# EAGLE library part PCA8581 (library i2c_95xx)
128 x 8-Bit EEPROM with I²C Bus Interface
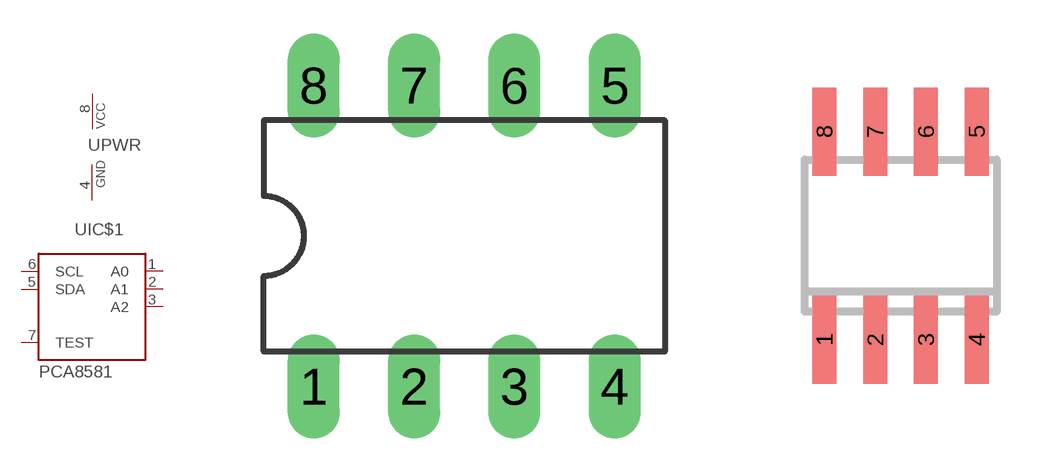
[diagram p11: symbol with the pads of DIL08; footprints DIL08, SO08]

Designator prefix -; gates IC$1=PCA8581 PWR=PWRN

## PCA8581P  [DIL08]
1  IC$1:A0  in
2  IC$1:A1  in
3  IC$1:A2  in
4  PWR:GND  pwr
5  IC$1:SDA
6  IC$1:SCL  in
7  IC$1:TEST
8  PWR:VCC  pwr

## PCA8581CP  [DIL08]
Pads as for DIL08

## PCA8581T  [SO08]
Pads as for DIL08

## PCA8581CT  [SO08]
Pads as for DIL08

## Footprint DIL08 (pad centres in mm)
drill 0.813 long: 1 -3.81,-3.81; 2 -1.27,-3.81; 3 1.27,-3.81; 4 3.81,-3.81; 5 3.81,3.81; 6 1.27,3.81; 7 -1.27,3.81; 8 -3.81,3.81

## Footprint SO08 (pad centres in mm)
smd 0.6 x 2.2: 1 -1.905,-2.6; 2 -0.635,-2.6; 3 0.635,-2.6; 4 1.905,-2.6; 5 1.905,2.6; 6 0.635,2.6; 7 -0.635,2.6; 8 -1.905,2.6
